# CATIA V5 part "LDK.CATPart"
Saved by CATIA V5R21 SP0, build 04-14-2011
Part number: LDK.SLDPRT
Bounding box of the stored display mesh (mm): x -1.362 to 1.338, y -0.976 to 1.024, z 2.1 to 2.7
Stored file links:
  C:\Users\user\Desktop\CATIA文件\0-最新文件\LDK\LDK.CATPart
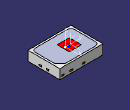
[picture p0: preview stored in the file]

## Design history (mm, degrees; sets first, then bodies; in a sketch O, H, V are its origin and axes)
AxisSystem1: origin (-0.0115, 0.0244, 2.7), X (0, 1, 0), Y (-1, 0, 0), Z (0, 0, 1)
Set1
  DatumSurface1 to DatumSurface42
  Line1: stored without definition
  Circle1: stored without definition
  Line2: stored without definition
  Circle2: stored without definition
  Line3: stored without definition
  Circle3: stored without definition
  Line4: stored without definition
  Circle4: stored without definition
  Line5: stored without definition
  Circle5: stored without definition
  Line6: stored without definition
  Circle6: stored without definition
  Line7: stored without definition
  Circle7: stored without definition
  Line8: stored without definition
  Line9: stored without definition
  Circle8: stored without definition
  Line10: stored without definition
  Line11: stored without definition
  Circle9: stored without definition
  Line12: stored without definition
  Line13: stored without definition
  Circle10: stored without definition
  Line14 to Line18: stored without definition
  Circle11: stored without definition
  Line19: stored without definition
  Circle12: stored without definition
  Line20: stored without definition
  Circle13: stored without definition
  Line21: stored without definition
  Circle14: stored without definition
  Line22: stored without definition
  Circle15: stored without definition
  Line23: stored without definition
  Circle16: stored without definition
  Line24: stored without definition
  Circle17: stored without definition
  Line25: stored without definition
  Circle18: stored without definition
  Line26: stored without definition
  Circle19: stored without definition
  Line27: stored without definition
  Circle20: stored without definition
  Line28 to Line30: stored without definition
  Circle21: stored without definition
  Line31: stored without definition
  Circle22: stored without definition
  Line32: stored without definition
  Circle23: stored without definition
  Line33: stored without definition
  Circle24: stored without definition
  Line34: stored without definition
  Line35: stored without definition
  Circle25: stored without definition
  Line36: stored without definition
  Circle26: stored without definition
  Line37: stored without definition
  Circle27: stored without definition
  Line38: stored without definition
  Circle28: stored without definition
  Line39: stored without definition
  Circle29: stored without definition
  Line40: stored without definition
  Circle30: stored without definition
  Line41: stored without definition
  Circle31: stored without definition
  Line42: stored without definition
  Circle32: stored without definition
  Line43: stored without definition
  Circle33: stored without definition
  Line44 to Line46: stored without definition
  Circle34: stored without definition
  Line47: stored without definition
  Circle35: stored without definition
  Line48: stored without definition
  Circle36: stored without definition
  Line49: stored without definition
  Circle37: stored without definition
  Line50: stored without definition
  Circle38: stored without definition
  Line51 to Line79: stored without definition
  DatumSurface43 to DatumSurface79
  Line80: stored without definition
  Circle39: stored without definition
  Line81: stored without definition
  Circle40: stored without definition
  Line82: stored without definition
  Circle41: stored without definition
  Line83: stored without definition
  Circle42: stored without definition
  Circle43: stored without definition
  Line84 to Line87: stored without definition
  Circle44: stored without definition
  Line88 to Line90: stored without definition
  Circle45: stored without definition
  Line91 to Line93: stored without definition
  Circle46: stored without definition
  Line94: stored without definition
  Line95: stored without definition
  Circle47: stored without definition
  Line96: stored without definition
  Circle48: stored without definition
  Line97: stored without definition
  Circle49: stored without definition
  Line98 to Line100: stored without definition
  Circle50: stored without definition
  Line101: stored without definition
  Circle51: stored without definition
  Line102: stored without definition
  Circle52: stored without definition
  Line103: stored without definition
  Circle53: stored without definition
  Line104: stored without definition
  Circle54: stored without definition
  Line105 to Line107: stored without definition
  Circle55: stored without definition
  Line108: stored without definition
  Circle56: stored without definition
  Line109 to Line112: stored without definition
  Circle57: stored without definition
  Line113: stored without definition
  Circle58: stored without definition
  Line114: stored without definition
  Circle59: stored without definition
  Line115 to Line117: stored without definition
  Circle60: stored without definition
  Line118: stored without definition
  Circle61: stored without definition
  Line119: stored without definition
  Circle62: stored without definition
  Line120: stored without definition
  Circle63: stored without definition
  Line121: stored without definition
  Circle64: stored without definition
  Line122 to Line124: stored without definition
  Circle65: stored without definition
  Line125: stored without definition
  Circle66: stored without definition
  Line126 to Line153: stored without definition
  DatumSurface80 to DatumSurface154
  DatumCurve1
  DatumCurve2
  Circle67: stored without definition
  Line154: stored without definition
  Circle68: stored without definition
  Line155: stored without definition
  Line156: stored without definition
  Circle69: stored without definition
  Line157: stored without definition
  Circle70: stored without definition
  Line158 to Line160: stored without definition
  Circle71: stored without definition
  Line161: stored without definition
  Circle72: stored without definition
  Line162 to Line164: stored without definition
  Circle73: stored without definition
  Line165: stored without definition
  Circle74: stored without definition
  Line166 to Line168: stored without definition
  Circle75: stored without definition
  Line169: stored without definition
  Circle76: stored without definition
  Line170: stored without definition
  Line171: stored without definition
  Circle77: stored without definition
  Line172: stored without definition
  Circle78: stored without definition
  Line173: stored without definition
  Circle79: stored without definition
  Line174 to Line176: stored without definition
  Circle80: stored without definition
  Line177: stored without definition
  Circle81: stored without definition
  Line178: stored without definition
  Circle82: stored without definition
  Line179: stored without definition
  Circle83: stored without definition
  Line180: stored without definition
  Circle84: stored without definition
  Line181 to Line183: stored without definition
  Circle85: stored without definition
  Line184: stored without definition
  Circle86: stored without definition
  Line185 to Line187: stored without definition
  Circle87: stored without definition
  Line188: stored without definition
  Line189: stored without definition
  Circle88: stored without definition
  Line190: stored without definition
  Line191: stored without definition
  Circle89: stored without definition
  Line192 to Line198: stored without definition
  Circle90: stored without definition
  Line199 to Line202: stored without definition
  Circle91: stored without definition
  Line203: stored without definition
  Line204: stored without definition
  Circle92: stored without definition
  Line205 to Line208: stored without definition
  Circle93: stored without definition
  Line209: stored without definition
  Line210: stored without definition
  Circle94: stored without definition
  Line211 to Line216: stored without definition
  Circle95: stored without definition
  Line217 to Line219: stored without definition
  Circle96: stored without definition
  Line220 to Line229: stored without definition
  Circle97: stored without definition
  Line230: stored without definition
  Circle98: stored without definition
  Line231: stored without definition
  Circle99: stored without definition
  Line232: stored without definition
  Circle100: stored without definition
  Line233: stored without definition
  Circle101: stored without definition
  Line234: stored without definition
  Circle102: stored without definition
  Line235: stored without definition
  Circle103: stored without definition
  Line236: stored without definition
  Circle104: stored without definition
  Line237 to Line245: stored without definition
  Circle105: stored without definition
  Line246: stored without definition
  Circle106: stored without definition
  Line247: stored without definition
  Circle107: stored without definition
  Line248: stored without definition
  Circle108: stored without definition
  Line249: stored without definition
  Circle109: stored without definition
  Line250: stored without definition
  Circle110: stored without definition
  Line251: stored without definition
  Circle111: stored without definition
  Line252: stored without definition
  Circle112: stored without definition
  Line253: stored without definition
  Circle113: stored without definition
  Line254: stored without definition
  Circle114: stored without definition
  Line255: stored without definition
  Circle115: stored without definition
  Line256: stored without definition
  Circle116: stored without definition
  Line257: stored without definition
  Circle117: stored without definition
  Line258 to Line260: stored without definition
  Circle118: stored without definition
  Line261: stored without definition
  Circle119: stored without definition
  Line262: stored without definition
  Circle120: stored without definition
  Line263: stored without definition
  Circle121: stored without definition
  Line264: stored without definition
  Circle122: stored without definition
  Line265: stored without definition
  Circle123: stored without definition
  Line266: stored without definition
  Circle124: stored without definition
  Line267: stored without definition
  Circle125: stored without definition
  Line268: stored without definition
  Circle126: stored without definition
  Line269: stored without definition
  Circle127: stored without definition
  Line270: stored without definition
  Circle128: stored without definition
  Line271 to Line273: stored without definition
  Circle129: stored without definition
  Line274: stored without definition
  Circle130: stored without definition
  Line275: stored without definition
  Circle131: stored without definition
  Line276: stored without definition
  Circle132: stored without definition
  Line277 to Line313: stored without definition
  DatumCurve3
  Line314: stored without definition
  DatumCurve4
  Line315: stored without definition
  DatumCurve5
  Line316: stored without definition
  DatumCurve6
  Line317: stored without definition
  DatumCurve7
  Line318 to Line323: stored without definition
  DatumCurve8
  Line324: stored without definition
  DatumCurve9
  Line325: stored without definition
  DatumCurve10
  Line326: stored without definition
  DatumCurve11
  Line327: stored without definition
  DatumCurve12
  Line328 to Line336: stored without definition
  Point1 "几何中心（测试原点）": type Between, FirstPoint vertex [face of DatumSurface148], SecondPoint vertex [face of DatumSurface147], Ratio 0.5
  Point2 "发光中心": type Between, FirstPoint vertex [face of DatumSurface154], SecondPoint vertex [face of DatumSurface154], Ratio 0.5
  Point3 "虚拟坐标": (-0.01, 0.212, -0.079), relative to Point1, in AxisSystem1
Body1 (main body)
